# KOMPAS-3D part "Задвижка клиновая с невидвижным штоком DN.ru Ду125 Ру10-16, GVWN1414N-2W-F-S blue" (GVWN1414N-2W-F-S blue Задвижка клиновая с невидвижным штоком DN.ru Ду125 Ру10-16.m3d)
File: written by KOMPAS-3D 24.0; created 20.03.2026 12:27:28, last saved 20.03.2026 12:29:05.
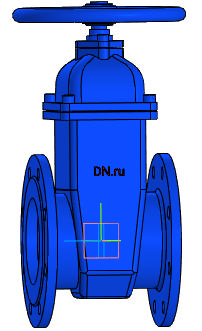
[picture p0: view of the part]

Document properties: Автор: R2D2; Полное имя файла: GVWN1414N-2W-F-S blue Задвижка клиновая с невидвижным штоком DN.ru Ду125 Ру10-16.cdw

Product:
- Part/product: Задвижка клиновая с невидвижным штоком DN.ru Ду125 Ру10-16  | designation GVWN1414N-2W-F-S blue
    Масса: 20
    Раздел спецификации: Прочие изделия
    Форматы листов документа: A2
    Примечание: D040-10583

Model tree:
1. Операция без истории:1

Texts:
  GVWN1414N-2W-F-S blue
